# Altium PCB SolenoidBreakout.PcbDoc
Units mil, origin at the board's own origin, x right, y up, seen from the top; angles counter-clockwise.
Board outline 1000 x 2300 mil, 2 copper layers (Top Layer, Bottom Layer); 7 components, 13 nets, 65 pads, 1 vias.
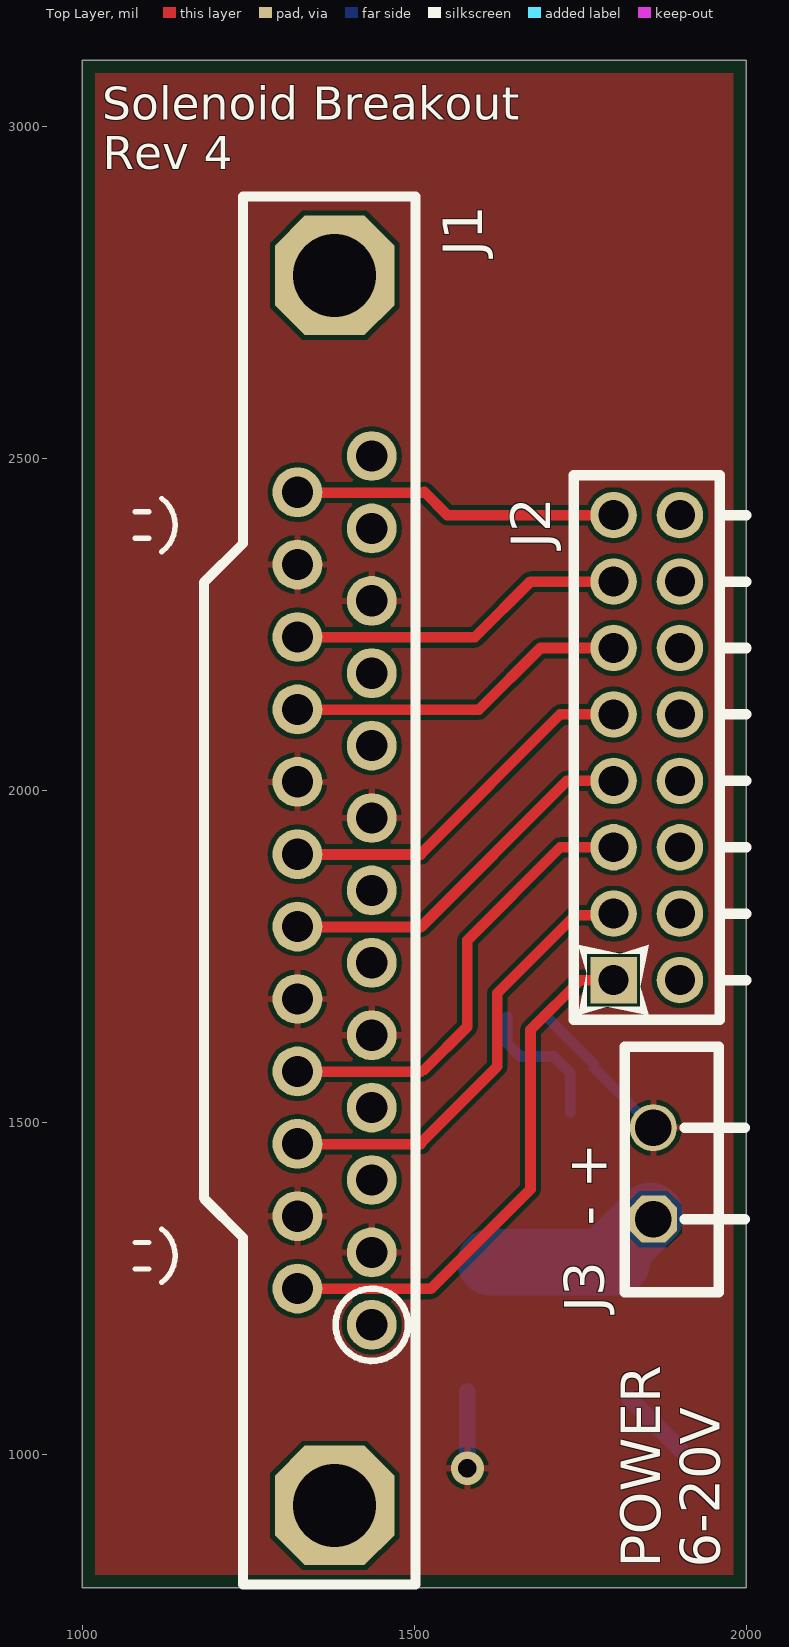
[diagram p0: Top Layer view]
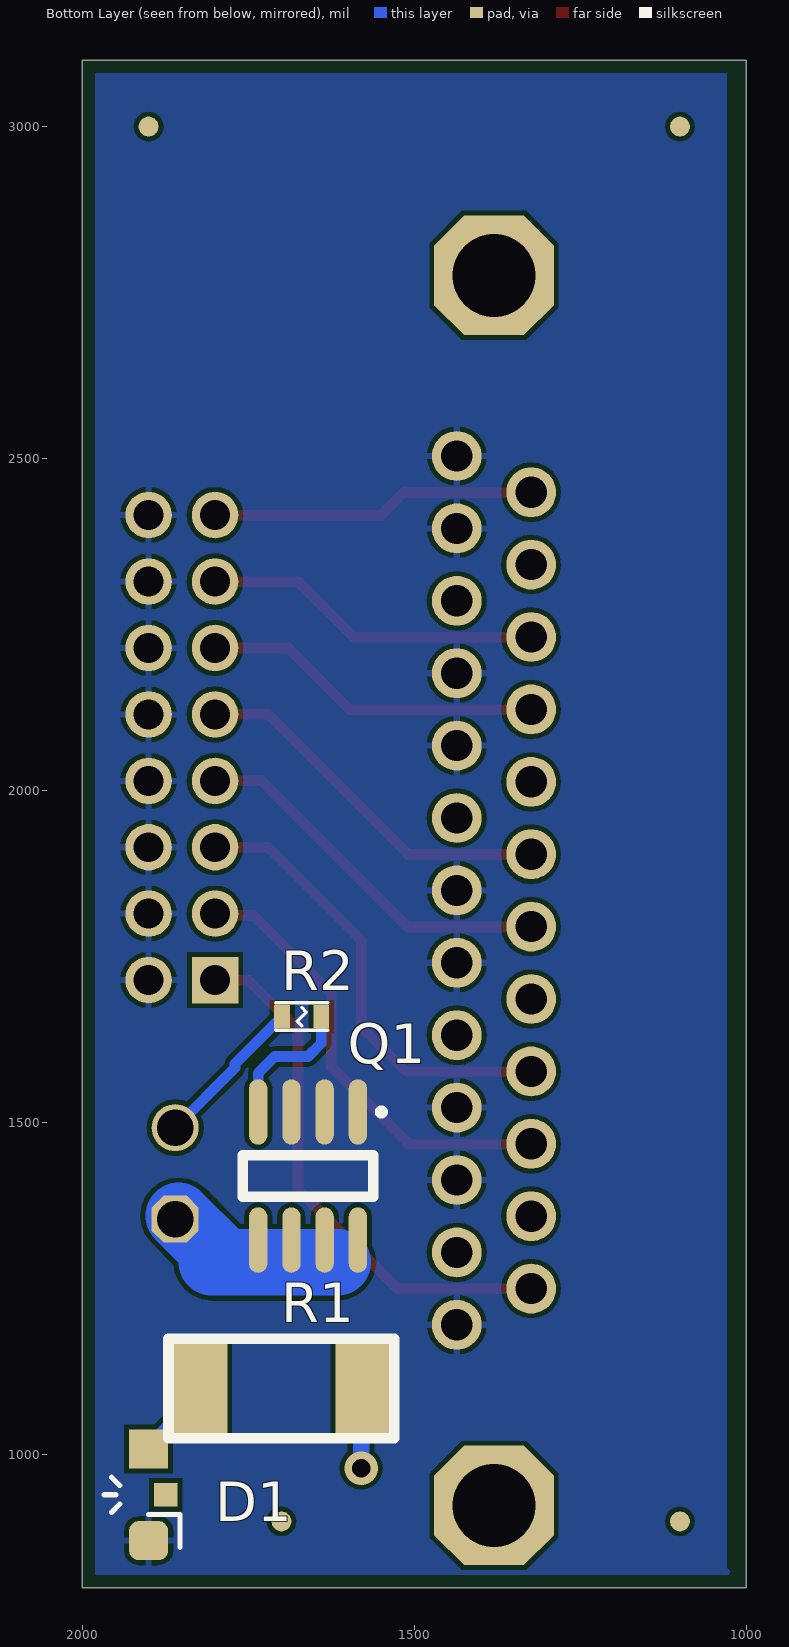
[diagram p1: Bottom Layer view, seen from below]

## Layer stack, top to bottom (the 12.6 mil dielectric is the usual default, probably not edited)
Top Layer: signal copper 1.4
Dielectric: dielectric 12.6, FR-4, Dk 4.8
Bottom Layer: signal copper 1.4

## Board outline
1000,3100 2000,3100 2000,800 1000,800

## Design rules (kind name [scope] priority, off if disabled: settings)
Clearance [All] p1: gap=7
HoleSize [All] p1: absolutevalues=TRUE maxlimit=150 minlimit=1 maxpercent=80.000 minpercent=20.000
PolygonConnect PolygonConnect_1 [(InComponent('Q1'))] p1: connectstyle=Direct reliefconductorwidth=10 reliefentries=4 polygonreliefangle="90 Angle"
PolygonConnect [All] p2: connectstyle=Relief reliefconductorwidth=10 reliefentries=4 polygonreliefangle="90 Angle"
RoutingVias [All] p1: holewidth=28 width=50 viastyle="Through Hole" minholewidth=28 minwidth=50 maxholewidth=100 maxwidth=1000
SolderMaskExpansion [All] p1: expansion=4
TestPointUsage [All] p1: valid=0 allowmultiple=FALSE
Testpoint [All] p1: side=15 testpointundercomponent=TRUE minsize=40 maxsize=100 preferedsize=60 minholesize=0 maxholesize=40 preferedholesize=32 testpointgrid=1 style=1023 order=0123456789
Width [All] p1: maxlimit=100 minlimit=12 preferedwidth=12
18 further rules are at their usual default settings.

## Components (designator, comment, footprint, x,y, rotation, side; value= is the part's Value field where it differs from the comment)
D1 "LTST-S320GKT" "LED1208RA LITEON" 1900,940 r0 bottom
J1 "DB25 Right Angle" "DB25 - RA" 1380,1850 r270 top
J2 "H100 2x8 POS THRU R/A" H100P2X8RA 1800,1715 r90 top
J3 "3.5mm Mini Header RA" "WAGO 734-162" 1860,1355 r90 top
Q1 "FDS8817NZ" "SO-8_M FET" 1660,1420 r270 bottom
R1 "1.2k ohm 2512 5%" R2512_C 1700,1100 r180 bottom
R2 "100k ohm 0603 1%" R0603_C 1669.53,1660 r0 bottom

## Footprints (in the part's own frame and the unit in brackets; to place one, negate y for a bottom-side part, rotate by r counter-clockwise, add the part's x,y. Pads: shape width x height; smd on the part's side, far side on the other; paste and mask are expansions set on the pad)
"DB25 - RA" [mil]
  round 75 hole 47: 1(654.02,55.98) 2(545,56) 3(436,56) 4(327,56) 5(218,56) 6(109,56) 7(0,56) 8(-109,56) 9(-218,56) 10(-327,56) 11(-436,56) 12(-545,56) 13(-654.02,55.98) 14(599.49,-55.98) 15(490.5,-56) 16(381.5,-56) 17(272.5,-56) 18(163.5,-56) 19(54.5,-56) 20(-54.5,-56) 21(-163.5,-56) 22(-272.5,-56) 23(-381.5,-56) 24(-490.5,-56) 25(-599.49,-55.98)
  oct 180x180 hole 125: SHELL(-925.98,0) SHELL(925.98,0)
  silkscreen extent -1045,-197 1045,122, body extent -1047,-610 1047,118, height 492
H100P2X8RA [mil] "Header 100mil, 8X2POS THRU RA"
  rect 70x70 hole 45: 1(0,0)
  round 70 hole 45: 2(0,-100) 3(100,0) 4(100,-100) 5(200,0) 6(200,-100) 7(300,0) 8(300,-100) 9(400,0) 10(400,-100) 11(500,0) 12(500,-100) 13(600,0) 14(600,-100) 15(700,0) 16(700,-100)
  silkscreen extent -60,-200 760,60, body extent -60,-490 760,10, height 240
"LED1208RA LITEON" [mm] "Lite ON Side Fire 1208 LED"
  rect 1.5x1.5 smd: A(0,-1.75)
  rrect50% 1.5x1.5 smd: K(0,1.75)
  rect 0.9x0.9 smd: ""(-0.65,0)
  silkscreen extent -1.2,-0.67 1.7,2
R0603_C [mm]
  rect 0.6x0.9 smd: 1(-0.75,0) 2(0.75,0)
  silkscreen extent -1,-0.53 1,0.53, body extent -0.75,-0.4 0.75,0.4, height 0.4
R2512_C [mil]
  rect 85x135 smd: 1(-124.02,0) 2(124.02,0)
  silkscreen extent -170,-75 170,75, body extent -125,-60 125,60, height 16
"SO-8_M FET" [mm] "8-Pin Plastic Small Outline Integrated Circuit 1.27 mm Pitch, IPC Low Density"
  oval 2.5x0.7 smd: D(2.45,-1.905) D(2.45,-0.635) D(2.45,0.635) D(2.45,1.905) G(-2.45,-1.905) S(-2.45,-0.635) S(-2.45,0.635) S(-2.45,1.905)
  silkscreen extent -2.57,-2.5 0.8,2.93, body extent -2,-2.5 2,2.5, height 1.75
"WAGO 734-162" [mm] "3.5mm 10 A Protected Header RA"
  oct 1.8x1.8 hole 1.4: 1(0,0)
  round 1.8 hole 1.4: 2(3.5,0)
  silkscreen extent -2.8,-3.5 6.6,1.1, body extent -2.86,-9.36 6.66,1.06, height 8.5

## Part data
D1: library part LTL-10233W, "T-1 3/4 Green"
J1: library part "DB25F RA Unthreaded", "DB25F RA Unthreaded .318\""
J2: library part "H100 2x8 POS THRU VERT"
J3: library part "WAGO 734-162", "3.5mm Header Protected against Mismating"
Q1: library part IRF7458TRPBF, "N-CH 30V 8SOIC"

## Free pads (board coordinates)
  round 30 smd far side mask+15: 0(1100,900) 0(1100,3000) 0(1700,900) 0(1900,3000) 0(3510,-820)

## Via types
v1: diameter 50, hole 28, Top Layer to Bottom Layer, 1 vias

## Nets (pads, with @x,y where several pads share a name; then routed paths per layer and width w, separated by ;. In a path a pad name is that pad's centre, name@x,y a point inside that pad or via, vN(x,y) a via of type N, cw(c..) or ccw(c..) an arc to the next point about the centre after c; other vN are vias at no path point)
DO1: J1.14 J2.1 | length 813.2
  Top Layer w16: J1.14@1320,1250 1324.02,1250 1525,1250 1675,1400 1675,1640 1750,1715 J2.1
DO2: J1.16 J2.3 | length 687.8
  Top Layer w16: J1.16@1321,1468 1324,1468 1510,1468 ; 1510,1470 1625,1585 1625,1695 1742.5,1812.5 1800,1812.5 J2.3@1802.5,1812.5
DO3: J1.17 J2.5 | length 688.3
  Top Layer w16: J1.17@1325,1577 1510,1577 ; 1515,1580 1580,1645 1580,1775 1720,1915 J2.5@1795,1915 ; J2.5@1795,1911.57 J2.5@1795,1915 ; J2.5 J2.5@1795,1915
DO4: J1.19 J2.7 | length 566.1
  Top Layer w16: J1.19@1325,1795 1510,1795 1730,2015 J2.7
DO5: J1.20 J2.9 | length 559.1
  Top Layer w16: J1.20@1327,1904 1510,1904 ; 1510,1905 1720,2115 1785,2115 1792.5,2122.5 J2.9@1795,2125
DO6: J1.22 J2.11 | length 514.5
  Top Layer w16: J1.22@1324,2122 1597,2122 1690,2215 J2.11
DO7: J1.23 J2.13 | length 524.8
  Top Layer w16: J1.23@1320,2230 1324,2230 J1.23@1337.05,2230 ; J1.23@1327,2231 1591,2231 1675,2315 J2.13
DO8: J1.25 J2.15 | length 486.5
  Top Layer w16: J1.25@1324.02,2449 1511,2449 ; 1515,2450 1550,2415 J2.15
GND: D1.K J1.1 J1.3 J1.4 J1.6 J1.7 J1.9 J1.10 J1.12 J1.13 J2.2 J2.4 J2.6 J2.8 J2.10 J2.12 J2.14 J2.16 Q1.S
NetD1_A: D1.A R1.1 | length 107.5
  Bottom Layer w25: R1.1@1824.02,1084.88 D1.A
NetJ3_1: J3.1 Q1.D | length 284.9
  Bottom Layer w100: 1615,1290 1635,1290 1685,1290 1735,1290 1795,1290 ; 1805,1290 1795,1290 ; J3.1@1855,1360 1795,1300 1795,1290
NetQ1_G: Q1.G R2.1 | length 212.2
  Bottom Layer w16: R2.1 1640,1620 1660,1600 1710,1600 1735,1575 Q1.G
VPOWER: J1.2 J1.5 J1.8 J1.11 J1.15 J1.18 J1.21 J1.24 J3.2 R1.2 R2.2 | length 349.9
  Bottom Layer w16: R2.2 1770,1589.06 1770,1582.8 J3.2
  Bottom Layer w25: v1(1580,980) R1.2@1580,1095.98
pads on no net: D1. J1.SHELL

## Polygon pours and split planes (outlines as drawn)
VPOWER on Top Layer "POWER" (solid, pour order 1000): 1020,3080 1980,3080 1980,820 1020,820 1020,3080
GND on Bottom Layer "GND" (solid, pour order 1001): 1029.51,3080 1980,3080 1980,820 1020,820 1029.51,829.83 1029.51,3080

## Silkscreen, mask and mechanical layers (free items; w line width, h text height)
Top Overlay:
  lines w8: 1080,1280 1100,1280 ; 1080,1320 1100,1320 ; 1080,2380 1100,2380 ; 1080,2420 1100,2420 ; 1120,1260 ccw(c1090,1300) 1120,1340 ; 1120,2360 ccw(c1090,2400) 1120,2440
  text "Solenoid Breakout" at 1030,3010 h50
  text "Rev 4" at 1031,2936 h50
  text "- +" at 1790,1345 h60 r90
  text "POWER" at 1870,830 h60 r90
  text "6-20V" at 1960,830 h60 r90
Mechanical 1:
  region: 3026.64,2502.71 5557.48,2502.71 5557.48,2489.38 3026.64,2489.38
  region: 3026.64,2529.39 5557.48,2529.39 5557.48,2516.05 3026.64,2516.05
  region: 5557.48,2529.39 5570.8,2529.39 5570.8,2516.05 5557.48,2516.05
  region: 5557.48,2502.71 5597.44,2502.71 5597.44,2489.38 5557.48,2489.38
  region: 3026.64,3037.84 5557.48,3037.84 5557.48,3024.51 3026.64,3024.51
  region: 3026.64,3064.52 5557.48,3064.52 5557.48,3051.18 3026.64,3051.18
  region: 5557.48,3064.52 5597.44,3064.52 5597.44,3051.18 5557.48,3051.18
  region: 5557.48,3037.84 5570.8,3037.84 5570.8,3024.51 5557.48,3024.51
  region: 5584.12,3024.51 5597.44,3024.51 5597.44,2529.39 5584.12,2529.39
  region: 5557.48,3024.51 5570.8,3024.51 5570.8,2529.39 5557.48,2529.39
  region: 3013.32,3024.51 3026.64,3024.51 3026.64,2529.39 3013.32,2529.39
  region: 2986.68,3024.51 3000,3024.51 3000,2529.39 2986.68,2529.39
  region: 5557.48,2529.39 5570.8,2529.39 5570.8,2516.05 5557.48,2516.05
  region: 5584.12,2529.39 5597.44,2529.39 5597.44,2489.38 5584.12,2489.38
  region: 2986.68,2529.39 3000,2529.39 3000,2489.38 2986.68,2489.38
  region: 3013.32,2529.39 3026.64,2529.39 3026.64,2516.05 3013.32,2516.05
  region: 5584.12,3064.52 5597.44,3064.52 5597.44,3024.51 5584.12,3024.51
  region: 5557.48,3037.84 5570.8,3037.84 5570.8,3024.51 5557.48,3024.51
  region: 2986.68,2502.71 3026.64,2502.71 3026.64,2489.38 2986.68,2489.38
  region: 3013.32,2529.39 3026.64,2529.39 3026.64,2516.05 3013.32,2516.05
  region: 3013.32,3037.84 3026.64,3037.84 3026.64,3024.51 3013.32,3024.51
  region: 2986.68,3064.52 3000,3064.52 3000,3024.51 2986.68,3024.51
  region: 3013.32,3037.84 3026.64,3037.84 3026.64,3024.51 3013.32,3024.51
  region: 2986.68,3064.52 3026.64,3064.52 3026.64,3051.18 2986.68,3051.18
  region: 4641.72,2192.91 4655.04,2192.91 4655.04,995.95 4641.72,995.95
  region: 3006.66,2206.24 6892.83,2206.24 6892.83,2192.91 3006.66,2192.91
  lines w1.67: 3006.66,2206.24 6892.83,2206.24 ; 4641.72,995.95 4641.72,2192.91
  lines w16: 1000,800 2000,800 2000,3100 1000,3100 1000,800
  text "P" at 3033.3,2900.95 h148.77
  text "r" at 3124.99,2900.95 h148.77
  text "o" at 3171.67,2900.95 h148.77
  text "j" at 3248.35,2900.95 h148.77
  text "e" at 3280.03,2900.95 h148.77
  text "c" at 3356.71,2900.95 h148.77
  text "t" at 3426.73,2900.95 h148.77
  text "P" at 4225.46,2900.95 h148.77
  text "h" at 4317.15,2900.95 h148.77
  text "o" at 4393.83,2900.95 h148.77
  text "e" at 4470.52,2900.95 h148.77
  text "n" at 4547.21,2900.95 h148.77
  text "i" at 4623.89,2900.95 h148.77
  text "x" at 4653.9,2900.95 h148.77
  text "B" at 3033.3,2729.24 h148.77
  text "o" at 3124.99,2729.24 h148.77
  text "a" at 3201.68,2729.24 h148.77
  text "r" at 3278.36,2729.24 h148.77
  text "d" at 3325.04,2729.24 h148.77
  text "S" at 4225.46,2729.24 h148.77
  text "o" at 4317.15,2729.24 h148.77
  text "l" at 4393.83,2729.24 h148.77
  text "e" at 4423.84,2729.24 h148.77
  text "n" at 4500.53,2729.24 h148.77
  text "o" at 4577.21,2729.24 h148.77
  text "i" at 4653.9,2729.24 h148.77
  text "d" at 4683.91,2729.24 h148.77
  text "B" at 4798.93,2729.24 h148.77
  text "r" at 4890.62,2729.24 h148.77
  text "e" at 4937.3,2729.24 h148.77
  text "a" at 5013.99,2729.24 h148.77
  text "k" at 5090.67,2729.24 h148.77
  text "o" at 5162.36,2729.24 h148.77
  text "u" at 5239.04,2729.24 h148.77
  text "t" at 5315.73,2729.24 h148.77
  text "R" at 3033.3,2560.87 h148.77
  text "e" at 3133.33,2560.87 h148.77
  text "v" at 3210.01,2560.87 h148.77
  text "4" at 4225.46,2560.87 h148.77
  text "C" at 3033.3,2237.73 h148.77
  text "o" at 3133.33,2237.73 h148.77
  text "n" at 3210.01,2237.73 h148.77
  text "s" at 3286.7,2237.73 h148.77
  text "t" at 3356.71,2237.73 h148.77
  text "r" at 3395.06,2237.73 h148.77
  text "u" at 3441.73,2237.73 h148.77
  text "c" at 3518.42,2237.73 h148.77
  text "t" at 3588.44,2237.73 h148.77
  text "i" at 3626.78,2237.73 h148.77
  text "o" at 3656.79,2237.73 h148.77
  text "n" at 3733.47,2237.73 h148.77
  text "L" at 3033.3,2066.02 h148.77
  text "a" at 3109.99,2066.02 h148.77
  text "y" at 3186.67,2066.02 h148.77
  text "e" at 3251.69,2066.02 h148.77
  text "r" at 3328.37,2066.02 h148.77
  text "s" at 3375.05,2066.02 h148.77
  text "2" at 4675.02,2066.02 h148.77
  text "F" at 3033.3,1894.31 h148.77
  text "i" at 3118.32,1894.31 h148.77
  text "n" at 3148.33,1894.31 h148.77
  text "i" at 3225.01,1894.31 h148.77
  text "s" at 3255.02,1894.31 h148.77
  text "h" at 3325.04,1894.31 h148.77
  text "e" at 3401.72,1894.31 h148.77
  text "d" at 3478.41,1894.31 h148.77
  text "T" at 3593.44,1894.31 h148.77
  text "h" at 3680.13,1894.31 h148.77
  text "i" at 3756.81,1894.31 h148.77
  text "c" at 3786.82,1894.31 h148.77
  text "k" at 3856.84,1894.31 h148.77
  text "n" at 3928.52,1894.31 h148.77
  text "e" at 4005.21,1894.31 h148.77
  text "s" at 4081.89,1894.31 h148.77
  text "s" at 4151.91,1894.31 h148.77
  text "0" at 4675.02,1894.31 h148.77
  text "6" at 4751.7,1894.31 h148.77
  text "3" at 4828.39,1894.31 h148.77
  text "+" at 4943.42,1894.31 h148.77
  text "/" at 5023.44,1894.31 h148.77
  text "-" at 5061.78,1894.31 h148.77
  text "3" at 5146.8,1894.31 h148.77
  text "0" at 5223.48,1894.31 h148.77
  text "%" at 5300.17,1894.31 h148.77
  text "S" at 3033.3,1722.6 h148.77
  text "o" at 3124.99,1722.6 h148.77
  text "l" at 3201.68,1722.6 h148.77
  text "d" at 3231.68,1722.6 h148.77
  text "e" at 3308.37,1722.6 h148.77
  text "r" at 3385.05,1722.6 h148.77
  text "M" at 3470.07,1722.6 h148.77
  text "a" at 3585.1,1722.6 h148.77
  text "s" at 3661.79,1722.6 h148.77
  text "k" at 3731.81,1722.6 h148.77
  text "U" at 4675.02,1722.6 h148.77
  text "n" at 4775.04,1722.6 h148.77
  text "s" at 4851.73,1722.6 h148.77
  text "p" at 4921.74,1722.6 h148.77
  text "e" at 4998.43,1722.6 h148.77
  text "c" at 5075.11,1722.6 h148.77
  text "i" at 5145.13,1722.6 h148.77
  text "f" at 5175.14,1722.6 h148.77
  text "i" at 5215.15,1722.6 h148.77
  text "e" at 5245.16,1722.6 h148.77
  text "d" at 5321.84,1722.6 h148.77
  text "C" at 5436.87,1722.6 h148.77
  text "o" at 5536.9,1722.6 h148.77
  text "l" at 5613.58,1722.6 h148.77
  text "o" at 5643.59,1722.6 h148.77
  text "r" at 5720.27,1722.6 h148.77
  text "T" at 4675.02,1550.89 h148.77
  text "o" at 4761.7,1550.89 h148.77
  text "p" at 4838.39,1550.89 h148.77
  text "&" at 4953.42,1550.89 h148.77
  text "B" at 5083.45,1550.89 h148.77
  text "o" at 5175.14,1550.89 h148.77
  text "t" at 5251.82,1550.89 h148.77
  text "t" at 5290.17,1550.89 h148.77
  text "o" at 5328.51,1550.89 h148.77
  text "m" at 5405.2,1550.89 h148.77
  text "S" at 3033.3,1379.18 h148.77
  text "i" at 3124.99,1379.18 h148.77
  text "l" at 3155,1379.18 h148.77
  text "k" at 3185,1379.18 h148.77
  text "S" at 3295.03,1379.18 h148.77
  text "c" at 3386.72,1379.18 h148.77
  text "r" at 3456.74,1379.18 h148.77
  text "e" at 3503.42,1379.18 h148.77
  text "e" at 3580.1,1379.18 h148.77
  text "n" at 3656.79,1379.18 h148.77
  text "U" at 4675.02,1379.18 h148.77
  text "n" at 4775.04,1379.18 h148.77
  text "s" at 4851.73,1379.18 h148.77
  text "p" at 4921.74,1379.18 h148.77
  text "e" at 4998.43,1379.18 h148.77
  text "c" at 5075.11,1379.18 h148.77
  text "i" at 5145.13,1379.18 h148.77
  text "f" at 5175.14,1379.18 h148.77
  text "i" at 5215.15,1379.18 h148.77
  text "e" at 5245.16,1379.18 h148.77
  text "d" at 5321.84,1379.18 h148.77
  text "C" at 5436.87,1379.18 h148.77
  text "o" at 5536.9,1379.18 h148.77
  text "l" at 5613.58,1379.18 h148.77
  text "o" at 5643.59,1379.18 h148.77
  text "r" at 5720.27,1379.18 h148.77
  text "T" at 4675.02,1207.47 h148.77
  text "o" at 4761.7,1207.47 h148.77
  text "p" at 4838.39,1207.47 h148.77
  text "O" at 4953.42,1207.47 h148.77
  text "n" at 5061.78,1207.47 h148.77
  text "l" at 5138.46,1207.47 h148.77
  text "y" at 5168.47,1207.47 h148.77
  text "-" at 5271.83,1207.47 h148.77
  text "I" at 5356.85,1207.47 h148.77
  text "g" at 5395.19,1207.47 h148.77
  text "n" at 5471.88,1207.47 h148.77
  text "o" at 5548.56,1207.47 h148.77
  text "r" at 5625.25,1207.47 h148.77
  text "e" at 5671.93,1207.47 h148.77
  text "B" at 5786.96,1207.47 h148.77
  text "o" at 5878.65,1207.47 h148.77
  text "t" at 5955.33,1207.47 h148.77
  text "t" at 5993.67,1207.47 h148.77
  text "o" at 6032.02,1207.47 h148.77
  text "m" at 6108.7,1207.47 h148.77
  text "S" at 6265.41,1207.47 h148.77
  text "i" at 6357.1,1207.47 h148.77
  text "l" at 6387.1,1207.47 h148.77
  text "k" at 6417.11,1207.47 h148.77
  text "C" at 3033.3,1035.76 h148.77
  text "o" at 3133.33,1035.76 h148.77
  text "p" at 3210.01,1035.76 h148.77
  text "p" at 3286.7,1035.76 h148.77
  text "e" at 3363.38,1035.76 h148.77
  text "r" at 3440.07,1035.76 h148.77
  text "W" at 3525.09,1035.76 h148.77
  text "e" at 3663.46,1035.76 h148.77
  text "i" at 3740.14,1035.76 h148.77
  text "g" at 3770.15,1035.76 h148.77
  text "h" at 3846.83,1035.76 h148.77
  text "t" at 3923.52,1035.76 h148.77
  text "1" at 4675.02,1035.76 h148.77
  text "/" at 4751.7,1035.76 h148.77
  text "2" at 4790.04,1035.76 h148.77
  text "o" at 4905.07,1035.76 h148.77
  text "z" at 4981.76,1035.76 h148.77
  text "o" at 5086.78,1035.76 h148.77
  text "r" at 5163.47,1035.76 h148.77
  text "t" at 5248.49,1035.76 h148.77
  text "h" at 5286.83,1035.76 h148.77
  text "i" at 5363.52,1035.76 h148.77
  text "c" at 5393.53,1035.76 h148.77
  text "k" at 5463.54,1035.76 h148.77
  text "e" at 5535.23,1035.76 h148.77
  text "r" at 5611.91,1035.76 h148.77
Drill Drawing:
  text ".legend" at 1000,3500 h60

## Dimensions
1000,800 to 1000,3100 on Mechanical 1
1000,800 to 2000,800 on Mechanical 1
